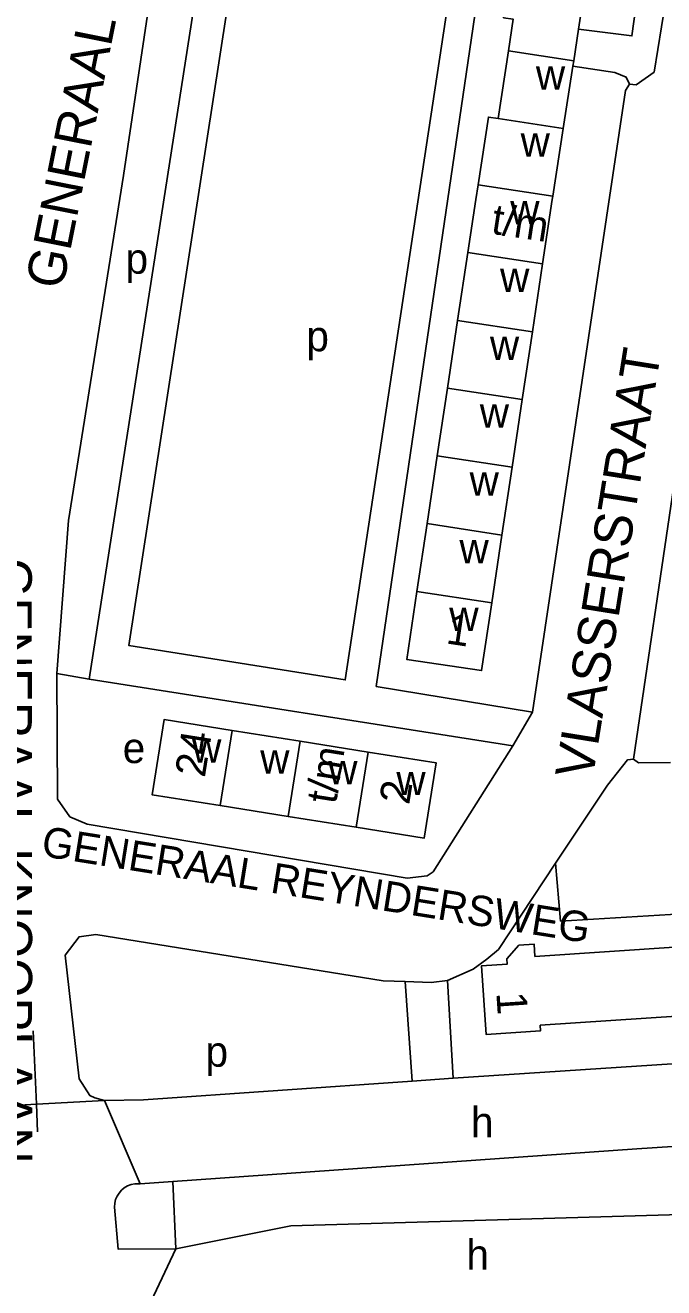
# Model space of a CAD drawing. Extents: x 159294 to 161936, y 384538 to 386517.
# Drawn here: x 161642.5 to 161726.7, y 385356.4 to 385523 of the extents above; entities that cross this region are included whole.
import ezdxf

# ---------------------------------------------------------------- set-up
doc = ezdxf.new("R2010")
doc.units = 0
for name, color, linetype in [('BLT_Basislijn', 7, 'Continuous'), ('BLT_Bebouwing', 7, 'Continuous'), ('BLT_Centroide', 7, 'Continuous'), ('BLT_Huisnummer_reeks', 7, 'Continuous'), ('BLT_Onderverdeling_panden', 7, 'Continuous'), ('BLT_Straatnaam', 7, 'Continuous'), ('BLT_Straatnaam_verkleind', 7, 'Continuous'), ('BLT_Vlakafsluiter', 7, 'Continuous')]:
    doc.layers.add(name, color=color, linetype=linetype)

msp = doc.modelspace()

# ---------------------------------------------------------------- linework, layer by layer
at = {"layer": 'BLT_Basislijn'}
for p, q in [((161666.66, 385538.05), (161650.88, 385436.72)), ((161728.02, 385462.23), (161722.68, 385426.15)), ((161646.63, 385437.48), (161650.88, 385436.72)), ((161650.88, 385436.72), (161706.79, 385427.93)), ((161706.79, 385427.93), (161709.38, 385432.38)), ((161712.41, 385412.43), (161713.05, 385404.78)), ((161771.9, 385408.41), (161713.05, 385404.78)), ((161693.48, 385383.71), (161692.56, 385396.82)), ((161698.17, 385396.99), (161698.91, 385384.07)), ((161643.51, 385390.34), (161643.93, 385380.65)), ((161698.91, 385384.07), (161773.44, 385388.95)), ((161693.48, 385383.71), (161698.91, 385384.07)), ((161643.93, 385380.65), (161644.09, 385377.02)), ((161661.92, 385370.45), (161657.62, 385370.15)), ((161661.92, 385370.45), (161662.31, 385361.57))]:
    msp.add_line(p, q, dxfattribs=at)
for points in [[(161725.55, 385566.96), (161712.8, 385568.99), (161708.66, 385569.33), (161703.78, 385538.11), (161688.75, 385435.76), (161709.38, 385432.38)], [(161742.4, 385565.18), (161740.05, 385548.5), (161738.14, 385543.82), (161732.25, 385538.19), (161729.23, 385533.65), (161727.33, 385528.81), (161725.42, 385516.79), (161723.06, 385515.12), (161722.14, 385515.21)], [(161646.63, 385437.48), (161648.18, 385457.64), (161655.43, 385503.15), (161660.44, 385536.76), (161661.65, 385538.42), (161666.66, 385538.05)], [(161716.8, 385531.24), (161723.27, 385530.28), (161723.59, 385529.86), (161722.47, 385521.56), (161715.44, 385522.44)], [(161669.86, 385530.03), (161656.13, 385441.15), (161684.66, 385436.61), (161698.19, 385525.73)], [(161722.14, 385515.21), (161721.74, 385516.13), (161720.23, 385516.75), (161714.68, 385517.57)], [(161709.38, 385432.38), (161721.63, 385514.37), (161722.14, 385515.21)], [(161646.63, 385437.48), (161646.7, 385420.9), (161648.36, 385418.58), (161650.65, 385417.59), (161692.82, 385410.49), (161695.46, 385410.78), (161696.25, 385411.3), (161706.79, 385427.93)], [(161712.41, 385412.43), (161719.25, 385422.74), (161721.89, 385426.06), (161722.68, 385426.15)], [(161722.68, 385426.15), (161723.33, 385425.66), (161727.55, 385425.74)], [(161698.17, 385396.99), (161701.55, 385398.46), (161703.35, 385399.79), (161704.87, 385401.07), (161712.41, 385412.43)], [(161692.56, 385396.82), (161689.66, 385396.91), (161651.79, 385403.02), (161649.57, 385402.73), (161647.72, 385400.33), (161649.57, 385384.01), (161651, 385381.79), (161651.63, 385381.5), (161652.9, 385381.15)], [(161698.17, 385396.99), (161696.02, 385396.72), (161692.56, 385396.82)], [(161652.9, 385381.15), (161658.06, 385381.23), (161693.48, 385383.71)], [(161791.88, 385380.87), (161775.64, 385379.01), (161759.39, 385377.16), (161723.12, 385374.75), (161661.92, 385370.45)], [(161654.22, 385367.09), (161654.26, 385367.58), (161654.37, 385368.06), (161654.57, 385368.51), (161654.83, 385368.93), (161655.15, 385369.3), (161655.53, 385369.62), (161655.96, 385369.87), (161656.42, 385370.04), (161656.9, 385370.14), (161657.4, 385370.16), (161657.62, 385370.15)], [(161662.31, 385361.57), (161677.49, 385364.59), (161792.55, 385367.95)], [(161654.22, 385367.09), (161654.74, 385361.51), (161662.31, 385361.57)]]:
    msp.add_lwpolyline(points, dxfattribs=at)
at = {"layer": 'BLT_Bebouwing'}
for p, q in [((161715.44, 385522.44), (161716.18, 385527.24)), ((161714.8, 385518.3), (161715.44, 385522.44)), ((161706.19, 385519.61), (161704.82, 385510.68)), ((161713.41, 385509.37), (161714.68, 385517.57)), ((161714.68, 385517.57), (161714.8, 385518.3)), ((161712.03, 385500.43), (161713.41, 385509.37)), ((161700.83, 385492.99), (161699.49, 385484.05)), ((161709.35, 385482.55), (161710.69, 385491.49)), ((161699.49, 385484.05), (161698.15, 385475.11)), ((161708.01, 385473.61), (161709.35, 385482.55)), ((161698.15, 385475.11), (161696.81, 385466.17)), ((161706.67, 385464.67), (161708.01, 385473.61)), ((161696.81, 385466.17), (161695.47, 385457.23)), ((161705.33, 385455.73), (161706.67, 385464.67)), ((161695.47, 385457.23), (161694.13, 385448.29)), ((161703.99, 385446.79), (161705.33, 385455.73)), ((161669.74, 385429.95), (161678.73, 385428.52)), ((161678.73, 385428.52), (161687.71, 385427.09)), ((161677.15, 385418.61), (161668.17, 385420.04)), ((161686.13, 385417.18), (161677.15, 385418.61))]:
    msp.add_line(p, q, dxfattribs=at)
for points in [[(161706.29, 385528.74), (161705.56, 385523.96), (161706.83, 385523.77), (161706.19, 385519.61)], [(161704.82, 385510.68), (161703.55, 385510.87), (161702.18, 385501.93)], [(161702.18, 385501.93), (161701.88, 385500), (161700.83, 385492.99)], [(161710.69, 385491.49), (161711.96, 385500), (161712.03, 385500.43)], [(161694.13, 385448.29), (161692.79, 385439.33), (161702.65, 385437.85), (161703.99, 385446.79)], [(161668.17, 385420.04), (161659.19, 385421.47), (161660.77, 385431.38), (161669.74, 385429.95)], [(161687.71, 385427.09), (161696.68, 385425.66), (161695.1, 385415.75), (161686.13, 385417.18)], [(161729, 385392.31), (161710.39, 385391.07), (161710.44, 385390.34), (161703.25, 385389.86), (161702.65, 385398.91), (161706.04, 385399.14), (161705.99, 385399.83), (161707.57, 385401.63), (161709.57, 385401.77), (161709.68, 385400.15), (161728.7, 385401.42)]]:
    msp.add_lwpolyline(points, dxfattribs=at)
at = {"layer": 'BLT_Onderverdeling_panden'}
for p, q in [((161714.8, 385518.3), (161706.19, 385519.61)), ((161713.41, 385509.37), (161704.82, 385510.68)), ((161712.03, 385500.43), (161702.18, 385501.93)), ((161710.69, 385491.49), (161700.83, 385492.99)), ((161709.35, 385482.55), (161699.49, 385484.05)), ((161708.01, 385473.61), (161698.15, 385475.11)), ((161706.67, 385464.67), (161696.81, 385466.17)), ((161705.33, 385455.73), (161695.47, 385457.23)), ((161703.99, 385446.79), (161694.13, 385448.29)), ((161668.17, 385420.04), (161669.74, 385429.95)), ((161677.15, 385418.61), (161678.73, 385428.52)), ((161686.13, 385417.18), (161687.71, 385427.09))]:
    msp.add_line(p, q, dxfattribs=at)
at = {"layer": 'BLT_Vlakafsluiter'}
for p, q in [((161643.93, 385380.65), (161652.9, 385381.15)), ((161657.62, 385370.15), (161652.9, 385381.15)), ((161631.57, 385379.96), (161643.93, 385380.65)), ((161662.31, 385361.57), (161658.31, 385353.09))]:
    msp.add_line(p, q, dxfattribs=at)

# ---------------------------------------------------------------- texts
at = {"layer": 'BLT_Centroide'}
for s, p in [('w', (161709.81, 385514.48)), ('w', (161707.8, 385505.66)), ('w', (161706.43, 385496.72)), ('p', (161655.69, 385490.2)), ('w', (161705.09, 385487.78)), ('p', (161679.54, 385479.97)), ('w', (161703.75, 385478.84)), ('w', (161702.41, 385469.91)), ('w', (161701.07, 385460.94)), ('w', (161699.73, 385452)), ('w', (161698.39, 385443.06)), ('e', (161655.32, 385425.65)), ('w', (161664.47, 385425.7)), ('w', (161673.45, 385424.27)), ('w', (161682.42, 385422.86)), ('w', (161691.41, 385421.42)), ('p', (161666.24, 385385.6)), ('h', (161701.25, 385376.29)), ('h', (161700.65, 385358.81))]:
    msp.add_text(s, height=4, dxfattribs=at).set_placement(p)
at = {"layer": 'BLT_Huisnummer_reeks'}
for s, rotation, p in [('t/m', 351.3392, (161703.81, 385495.5)), ('1', 351.4775, (161697.85, 385441.45)), ('24', 80.9526, (161666.14, 385423.65)), ('t/m', 80.9517, (161683.44, 385420.15)), ('2', 80.946, (161693.09, 385420.06)), ('1', 273.8061, (161704.59, 385395.34))]:
    msp.add_text(s, height=4, rotation=rotation, dxfattribs=at).set_placement(p)
at = {"layer": 'BLT_Straatnaam'}
for s, height, rotation, p in [('GENERAAL COENDERSLAAN', 5, 78.7447, (161647.37, 385487.98)), ('VLASSERSTRAAT', 5, 80.897, (161717.28, 385423.39)), ('GENERAAL KNOOPLAAN', 4.9999, 270.0517, (161638.32, 385452.68))]:
    msp.add_text(s, height=height, rotation=rotation, dxfattribs=at).set_placement(p)
at = {"layer": 'BLT_Straatnaam_verkleind'}
msp.add_text('GENERAAL REYNDERSWEG', height=3.9999, rotation=350.9324, dxfattribs=at).set_placement((161644.44, 385413.41))

doc.saveas('drawing.dxf')
